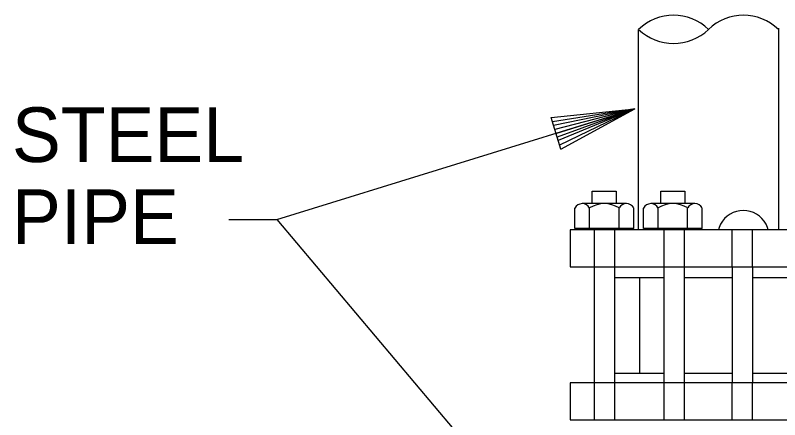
# Model space of a CAD drawing. Extents: x 9999.96 to 10005.26, y 9999.88 to 10002.38.
# Drawn here: x 10001.2111 to 10001.3506, y 10000.7017 to 10000.7757 of the extents above; entities that cross this region are included whole.
import ezdxf

# ---------------------------------------------------------------- set-up
doc = ezdxf.new("R2010")
doc.units = 0
doc.layers.add('Level 2', color=7, linetype='Continuous')

msp = doc.modelspace()

# ---------------------------------------------------------------- linework, layer by layer
at = {"layer": 'Level 2'}
for p, q in [((10001.324864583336, 10000.736416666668), (10001.324864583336, 10000.773083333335)), ((10001.350479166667, 10000.736416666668), (10001.350479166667, 10000.773302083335)), ((10001.308885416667, 10000.756979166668), (10001.32415625, 10000.758531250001)), ((10001.32415625, 10000.758531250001), (10001.309125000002, 10000.756187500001)), ((10001.32415625, 10000.758531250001), (10001.309322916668, 10000.755489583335)), ((10001.32415625, 10000.758531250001), (10001.309552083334, 10000.754781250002)), ((10001.309770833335, 10000.754062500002), (10001.32415625, 10000.758531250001)), ((10001.32415625, 10000.758531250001), (10001.309989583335, 10000.753395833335)), ((10001.32415625, 10000.758531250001), (10001.310166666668, 10000.752750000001)), ((10001.32415625, 10000.758531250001), (10001.310437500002, 10000.751947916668)), ((10001.310656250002, 10000.751218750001), (10001.32415625, 10000.758531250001)), ((10001.310656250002, 10000.751218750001), (10001.308885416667, 10000.756979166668)), ((10001.313239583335, 10000.7366875), (10001.313239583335, 10000.740395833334)), ((10001.322625, 10000.741239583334), (10001.314583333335, 10000.741239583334)), ((10001.315916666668, 10000.7366875), (10001.315916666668, 10000.740427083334)), ((10001.321312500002, 10000.7366875), (10001.321312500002, 10000.740427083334)), ((10001.323979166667, 10000.7366875), (10001.323979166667, 10000.740427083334)), ((10001.325750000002, 10000.7366875), (10001.325750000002, 10000.740395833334)), ((10001.335135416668, 10000.741239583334), (10001.327093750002, 10000.741239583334)), ((10001.328427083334, 10000.7366875), (10001.328427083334, 10000.740427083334)), ((10001.333822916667, 10000.7366875), (10001.333822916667, 10000.740427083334)), ((10001.336489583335, 10000.7366875), (10001.336489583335, 10000.740427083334)), ((10001.323979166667, 10000.7366875), (10001.313239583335, 10000.7366875)), ((10001.316822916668, 10000.729687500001), (10001.316822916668, 10000.736416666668)), ((10001.320541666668, 10000.729687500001), (10001.320541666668, 10000.736416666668)), ((10001.336489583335, 10000.7366875), (10001.325750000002, 10000.7366875)), ((10001.329552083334, 10000.729687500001), (10001.329552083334, 10000.736416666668)), ((10001.333270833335, 10000.729687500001), (10001.333270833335, 10000.736416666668)), ((10001.341958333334, 10000.729687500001), (10001.341958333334, 10000.736416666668)), ((10001.345677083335, 10000.729687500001), (10001.345677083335, 10000.736416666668)), ((10001.316822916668, 10000.708458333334), (10001.316822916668, 10000.729687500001)), ((10001.320541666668, 10000.708458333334), (10001.320541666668, 10000.729687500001)), ((10001.329552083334, 10000.708458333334), (10001.329552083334, 10000.729687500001)), ((10001.333270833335, 10000.708458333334), (10001.333270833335, 10000.729687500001)), ((10001.341958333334, 10000.729687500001), (10001.341958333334, 10000.708458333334)), ((10001.345677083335, 10000.729687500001), (10001.345677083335, 10000.708458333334)), ((10001.329520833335, 10000.727666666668), (10001.320541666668, 10000.727666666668)), ((10001.325020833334, 10000.727656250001), (10001.325020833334, 10000.710312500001)), ((10001.34196875, 10000.727666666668), (10001.333260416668, 10000.727666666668)), ((10001.354927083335, 10000.727666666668), (10001.345708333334, 10000.727666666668)), ((10001.320541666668, 10000.710250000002), (10001.329520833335, 10000.710250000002)), ((10001.333260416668, 10000.710250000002), (10001.34196875, 10000.710250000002)), ((10001.345708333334, 10000.710250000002), (10001.354927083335, 10000.710250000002)), ((10001.316822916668, 10000.701750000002), (10001.316822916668, 10000.708479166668)), ((10001.320541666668, 10000.701750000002), (10001.320541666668, 10000.708479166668)), ((10001.329552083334, 10000.701750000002), (10001.329552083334, 10000.708479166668)), ((10001.333270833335, 10000.701750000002), (10001.333270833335, 10000.708479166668)), ((10001.341958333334, 10000.701750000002), (10001.341958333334, 10000.708479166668)), ((10001.345677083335, 10000.701750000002), (10001.345677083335, 10000.708479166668))]:
    msp.add_line(p, q, dxfattribs=at)
for points in [[(10001.25009375, 10000.738333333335), (10001.258843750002, 10000.738333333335), (10001.32415625, 10000.758531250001)], [(10001.316395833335, 10000.741260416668), (10001.316395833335, 10000.743520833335), (10001.320802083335, 10000.743520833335), (10001.320802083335, 10000.741260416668)], [(10001.32890625, 10000.741260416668), (10001.32890625, 10000.743520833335), (10001.3333125, 10000.743520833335), (10001.3333125, 10000.741260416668)], [(10001.348500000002, 10000.736416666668), (10001.348375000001, 10000.736875), (10001.348125, 10000.737458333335), (10001.347791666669, 10000.738010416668), (10001.347385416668, 10000.738500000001), (10001.346927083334, 10000.738937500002), (10001.34640625, 10000.739302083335), (10001.345843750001, 10000.73959375), (10001.345239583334, 10000.739812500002), (10001.344614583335, 10000.7399375), (10001.343979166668, 10000.739989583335), (10001.34334375, 10000.7399375), (10001.342718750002, 10000.739812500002), (10001.342114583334, 10000.73959375), (10001.341552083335, 10000.739302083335), (10001.341031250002, 10000.738937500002), (10001.340572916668, 10000.738500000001), (10001.340166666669, 10000.738010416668), (10001.339843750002, 10000.737458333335), (10001.339583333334, 10000.736875), (10001.339458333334, 10000.736416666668)], [(10001.258843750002, 10000.738333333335), (10001.312708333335, 10000.674375)]]:
    msp.add_lwpolyline(points, dxfattribs=at)
for points in [[(10001.312395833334, 10000.729687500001), (10001.3630625, 10000.729687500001), (10001.3630625, 10000.736416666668), (10001.312395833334, 10000.736416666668)], [(10001.312395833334, 10000.701729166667), (10001.3630625, 10000.701729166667), (10001.3630625, 10000.708458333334), (10001.312395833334, 10000.708458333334)]]:
    msp.add_lwpolyline(points, close=True, dxfattribs=at)
for centre, radius, start, end in [((10001.331244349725, 10000.76648278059), 0.009179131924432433, 45.97749722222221, 134.02119166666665), ((10001.344002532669, 10000.76648278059), 0.009179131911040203, 45.97880833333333, 134.0225027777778), ((10001.331244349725, 10000.779683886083), 0.009179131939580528, 225.97880833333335, 314.0225027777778), ((10001.314588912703, 10000.739727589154), 0.0015017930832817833, 28.160902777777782, 153.2173138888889), ((10001.318617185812, 10000.736278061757), 0.004961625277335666, 57.057025, 122.99384166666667), ((10001.322643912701, 10000.739738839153), 0.0015017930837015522, 27.965813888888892, 152.1123), ((10001.327099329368, 10000.739727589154), 0.0015017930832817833, 28.160902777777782, 153.2173138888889), ((10001.33112760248, 10000.736278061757), 0.004961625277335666, 57.057025, 122.99384166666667), ((10001.335154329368, 10000.739738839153), 0.0015017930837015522, 27.965813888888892, 152.1123)]:
    msp.add_arc(centre, radius, start, end, dxfattribs=at)

# ---------------------------------------------------------------- texts
for s, p in [('STEEL', (10001.210479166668, 10000.748833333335)), ('PIPE', (10001.210479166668, 10000.733833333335))]:
    msp.add_text(s, height=0.010000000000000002, dxfattribs=at).set_placement(p)

doc.saveas('drawing.dxf')
